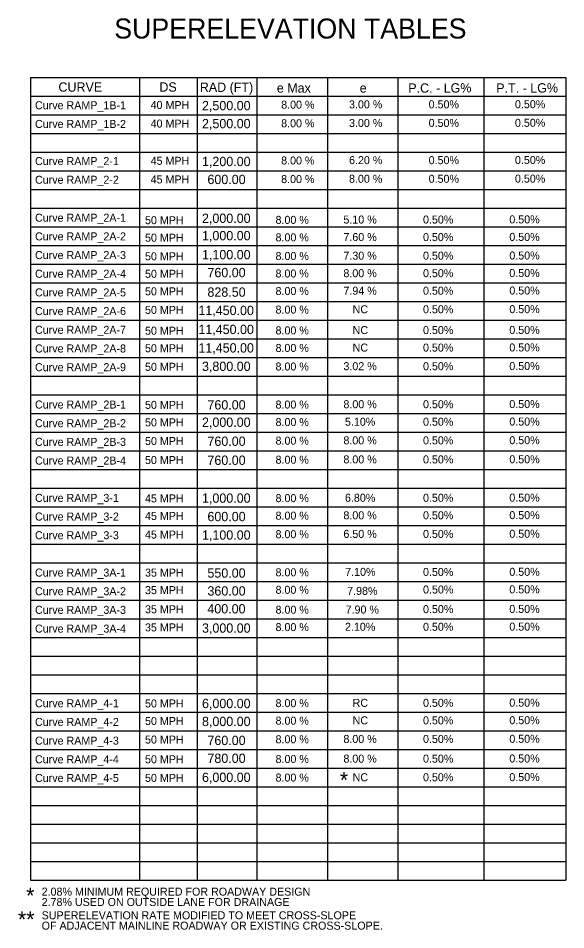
# Model space of a CAD drawing. Extents: x 1609180 to 1612299, y 1092317 to 1096201.
# Drawn here: x 1610132 to 1610543, y 1095399 to 1096082 of the extents above; entities that cross this region are included whole.
import ezdxf

# ---------------------------------------------------------------- set-up
doc = ezdxf.new("R2010")
doc.units = 0
for name, color, linetype in [('Level 1', 7, 'Continuous'), ('RD_HC_Data_50', 7, 'Continuous'), ('RD_SHT_TX', 7, 'Continuous')]:
    doc.layers.add(name, color=color, linetype=linetype)

msp = doc.modelspace()

# ---------------------------------------------------------------- linework, layer by layer
at = {"layer": 'RD_SHT_TX'}
for p, q in [((1610141.1, 1096037.78), (1610141.1, 1095435.78)), ((1610141.1, 1096037.78), (1610542.55, 1096037.78)), ((1610222.73, 1096037.78), (1610222.73, 1095435.78)), ((1610266.09, 1096037.78), (1610266.09, 1095435.78)), ((1610310.86, 1096037.78), (1610310.86, 1095435.78)), ((1610363.76, 1096037.78), (1610363.76, 1095435.78)), ((1610416.66, 1096037.78), (1610416.66, 1095435.78)), ((1610481.04, 1096037.78), (1610481.04, 1095435.78)), ((1610542.55, 1096037.78), (1610542.55, 1095435.78)), ((1610141.1, 1096023.78), (1610542.55, 1096023.78)), ((1610141.1, 1096009.78), (1610542.55, 1096009.78)), ((1610141.1, 1095995.78), (1610542.55, 1095995.78)), ((1610141.1, 1095981.78), (1610542.55, 1095981.78)), ((1610141.1, 1095967.78), (1610542.55, 1095967.78)), ((1610141.1, 1095953.78), (1610542.55, 1095953.78)), ((1610141.1, 1095939.78), (1610542.55, 1095939.78)), ((1610141.1, 1095925.78), (1610542.55, 1095925.78)), ((1610141.1, 1095911.78), (1610542.55, 1095911.78)), ((1610141.1, 1095897.78), (1610542.55, 1095897.78)), ((1610141.1, 1095883.78), (1610542.55, 1095883.78)), ((1610141.1, 1095869.78), (1610542.55, 1095869.78)), ((1610141.1, 1095855.78), (1610542.55, 1095855.78)), ((1610141.1, 1095841.78), (1610542.55, 1095841.78)), ((1610141.1, 1095827.78), (1610542.55, 1095827.78)), ((1610141.1, 1095813.78), (1610542.55, 1095813.78)), ((1610141.1, 1095799.78), (1610542.55, 1095799.78)), ((1610141.1, 1095785.78), (1610542.55, 1095785.78)), ((1610141.1, 1095771.78), (1610542.55, 1095771.78)), ((1610141.1, 1095757.78), (1610542.55, 1095757.78)), ((1610141.1, 1095743.78), (1610542.55, 1095743.78)), ((1610141.1, 1095729.78), (1610542.55, 1095729.78)), ((1610141.1, 1095715.78), (1610542.55, 1095715.78)), ((1610141.1, 1095701.78), (1610542.55, 1095701.78)), ((1610141.1, 1095687.78), (1610542.55, 1095687.78)), ((1610141.1, 1095673.78), (1610542.55, 1095673.78)), ((1610141.1, 1095659.78), (1610542.55, 1095659.78)), ((1610141.1, 1095645.78), (1610542.55, 1095645.78)), ((1610141.1, 1095631.78), (1610542.55, 1095631.78)), ((1610141.1, 1095617.78), (1610542.55, 1095617.78)), ((1610141.1, 1095603.78), (1610542.55, 1095603.78)), ((1610141.1, 1095589.78), (1610542.55, 1095589.78)), ((1610141.1, 1095575.78), (1610542.55, 1095575.78)), ((1610141.1, 1095561.78), (1610542.55, 1095561.78)), ((1610141.1, 1095547.78), (1610542.55, 1095547.78)), ((1610141.1, 1095533.78), (1610542.55, 1095533.78)), ((1610141.1, 1095519.78), (1610542.55, 1095519.78)), ((1610141.1, 1095505.78), (1610542.55, 1095505.78)), ((1610141.1, 1095491.78), (1610542.55, 1095491.78)), ((1610141.1, 1095477.78), (1610542.55, 1095477.78)), ((1610141.1, 1095463.78), (1610542.55, 1095463.78)), ((1610141.1, 1095449.78), (1610542.55, 1095449.78)), ((1610141.1, 1095435.78), (1610542.55, 1095435.78))]:
    msp.add_line(p, q, dxfattribs=at)

# ---------------------------------------------------------------- texts
at = {"layer": 'Level 1'}
for s, p in [('Curve RAMP_2B-4            ', (1610144.47, 1095747.49)), ('Curve RAMP_3-1             ', (1610144.47, 1095719.49)), ('Curve RAMP_3-2             ', (1610144.47, 1095705.49))]:
    msp.add_text(s, height=6, dxfattribs=at).set_placement(p)
at = {"layer": 'RD_HC_Data_50'}
for s, p in [('P.C. - LG%', (1610424.45, 1096026.23)), ('P.T. - LG%', (1610490.43, 1096026.23))]:
    msp.add_text(s, height=7, rotation=0.2225, dxfattribs=at).set_placement(p)
for s, p in [('3.00 %', (1610379.99, 1096014.54)), ('0.50%', (1610439.7, 1096014.54)), ('0.50%', (1610504.43, 1096014.65)), ('40 MPH', (1610231.18, 1096014.07)), ('8.00 %', (1610329.08, 1096014.3)), ('40 MPH', (1610231.18, 1096000.12)), ('8.00 %', (1610329.08, 1096000.35)), ('3.00 %', (1610379.99, 1096000.59)), ('0.50%', (1610439.7, 1096000.59)), ('0.50%', (1610504.43, 1096000.71)), ('45 MPH', (1610231.18, 1095972.22)), ('8.00 %', (1610329.08, 1095972.46)), ('6.20 %', (1610379.99, 1095972.69)), ('0.50%', (1610439.7, 1095972.69)), ('0.50%', (1610504.43, 1095972.81)), ('45 MPH', (1610231.18, 1095958.27)), ('8.00 %', (1610329.08, 1095958.51)), ('8.00 %', (1610379.99, 1095958.74)), ('0.50%', (1610439.7, 1095958.74)), ('0.50%', (1610504.43, 1095958.86)), ('50 MPH', (1610226.97, 1095927.7)), ('8.00 %', (1610324.87, 1095927.93)), ('5.10 %', (1610375.78, 1095928.17)), ('0.50%', (1610435.48, 1095928.17)), ('0.50%', (1610500.22, 1095928.28)), ('50 MPH', (1610226.97, 1095914.57)), ('8.00 %', (1610324.87, 1095914.8)), ('7.60 %', (1610375.78, 1095915.04)), ('0.50%', (1610435.48, 1095915.04)), ('0.50%', (1610500.22, 1095915.15)), ('50 MPH', (1610226.97, 1095900.62)), ('8.00 %', (1610324.87, 1095900.85)), ('7.30 %', (1610375.78, 1095901.09)), ('0.50%', (1610435.48, 1095901.09)), ('0.50%', (1610500.22, 1095901.21)), ('50 MPH', (1610226.97, 1095887.49)), ('8.00 %', (1610324.87, 1095887.73)), ('8.00 %', (1610375.78, 1095887.96)), ('0.50%', (1610435.48, 1095887.96)), ('0.50%', (1610500.22, 1095888.08)), ('50 MPH', (1610226.97, 1095874.36)), ('8.00 %', (1610324.87, 1095874.6)), ('7.94 %', (1610375.78, 1095874.83)), ('0.50%', (1610435.48, 1095874.83)), ('0.50%', (1610500.22, 1095874.95)), ('50 MPH', (1610226.97, 1095860.42)), ('8.00 %', (1610324.87, 1095860.65)), ('NC', (1610382.68, 1095860.89)), ('0.50%', (1610435.48, 1095860.89)), ('0.50%', (1610500.22, 1095861)), ('50 MPH', (1610226.97, 1095844.83)), ('8.00 %', (1610324.87, 1095845.06)), ('NC', (1610382.68, 1095845.3)), ('0.50%', (1610435.48, 1095845.3)), ('0.50%', (1610500.22, 1095845.41)), ('50 MPH', (1610226.97, 1095831.7)), ('8.00 %', (1610324.87, 1095831.93)), ('NC', (1610382.68, 1095832.17)), ('0.50%', (1610435.48, 1095832.17)), ('0.50%', (1610500.22, 1095832.29)), ('50 MPH', (1610226.97, 1095817.75)), ('8.00 %', (1610324.87, 1095817.99)), ('3.02 %', (1610375.78, 1095818.22)), ('0.50%', (1610435.48, 1095818.22)), ('0.50%', (1610500.22, 1095818.34)), ('50 MPH', (1610226.97, 1095789.24)), ('8.00 %', (1610324.87, 1095789.47)), ('8.00 %', (1610375.78, 1095789.71)), ('0.50%', (1610435.48, 1095789.71)), ('0.50%', (1610500.22, 1095789.83)), ('50 MPH', (1610226.97, 1095776.11)), ('8.00 %', (1610324.87, 1095776.35)), ('5.10%', (1610376.94, 1095776.58)), ('0.50%', (1610435.48, 1095776.58)), ('0.50%', (1610500.22, 1095776.7)), ('50 MPH', (1610226.97, 1095762.16)), ('8.00 %', (1610324.87, 1095762.4)), ('8.00 %', (1610375.78, 1095762.63)), ('0.50%', (1610435.48, 1095762.63)), ('0.50%', (1610500.22, 1095762.75)), ('8.00 %', (1610324.87, 1095748.1)), ('8.00 %', (1610375.78, 1095748.33)), ('0.50%', (1610435.48, 1095748.33)), ('0.50%', (1610500.22, 1095748.45)), ('50 MPH', (1610226.97, 1095747.86)), ('45 MPH', (1610226.97, 1095719.09)), ('8.00 %', (1610324.87, 1095719.32)), ('6.80%', (1610376.94, 1095719.56)), ('0.50%', (1610435.48, 1095719.56)), ('0.50%', (1610500.22, 1095719.67)), ('45 MPH', (1610226.97, 1095705.96)), ('8.00 %', (1610324.87, 1095706.19)), ('8.00 %', (1610375.78, 1095706.43)), ('0.50%', (1610435.48, 1095706.43)), ('0.50%', (1610500.22, 1095706.55)), ('45 MPH', (1610226.97, 1095692.01)), ('8.00 %', (1610324.87, 1095692.25)), ('6.50 %', (1610375.78, 1095692.48)), ('0.50%', (1610435.48, 1095692.48)), ('0.50%', (1610500.22, 1095692.6)), ('35 MPH', (1610226.97, 1095663.46)), ('8.00 %', (1610324.87, 1095663.7)), ('0.50%', (1610435.48, 1095663.93)), ('0.50%', (1610500.22, 1095664.05)), ('35 MPH', (1610226.97, 1095650.33)), ('8.00 %', (1610324.87, 1095650.57)), ('0.50%', (1610435.48, 1095650.8)), ('0.50%', (1610500.22, 1095650.92)), ('35 MPH', (1610226.97, 1095635.97)), ('8.00 %', (1610324.87, 1095635.66)), ('7.90 %', (1610377.43, 1095635.78)), ('0.50%', (1610435.48, 1095636.11)), ('0.50%', (1610500.22, 1095636.23)), ('35 MPH', (1610226.97, 1095622.39)), ('8.00 %', (1610324.87, 1095622.62)), ('2.10%', (1610376.94, 1095622.85)), ('0.50%', (1610435.48, 1095622.85)), ('0.50%', (1610500.22, 1095622.97)), ('50 MPH', (1610226.97, 1095565.36)), ('8.00 %', (1610324.87, 1095565.6)), ('RC', (1610382.68, 1095565.83)), ('0.50%', (1610435.48, 1095565.83)), ('0.50%', (1610500.22, 1095565.95)), ('50 MPH', (1610226.97, 1095552.23)), ('8.00 %', (1610324.87, 1095552.47)), ('NC', (1610382.68, 1095552.7)), ('0.50%', (1610435.48, 1095552.7)), ('0.50%', (1610500.22, 1095552.82)), ('50 MPH', (1610226.97, 1095538.29)), ('8.00 %', (1610324.87, 1095538.52)), ('8.00 %', (1610375.78, 1095538.75)), ('0.50%', (1610435.48, 1095538.75)), ('0.50%', (1610500.22, 1095538.87)), ('50 MPH', (1610226.97, 1095523.52)), ('8.00 %', (1610324.87, 1095523.75)), ('8.00 %', (1610375.78, 1095523.99)), ('0.50%', (1610435.48, 1095523.99)), ('0.50%', (1610500.22, 1095524.1)), ('50 MPH', (1610226.97, 1095509.57)), ('8.00 %', (1610324.87, 1095509.8)), ('NC', (1610382.68, 1095510.04)), ('0.50%', (1610435.48, 1095510.04)), ('0.50%', (1610500.22, 1095510.15))]:
    msp.add_text(s, height=6, dxfattribs=at).set_placement(p)
at = {"layer": 'RD_SHT_TX'}
for s, height, p in [('SUPERELEVATION TABLES', 15, (1610203.9, 1096066.88)), ('RAD (FT)', 7, (1610268.07, 1096026.9)), ('CURVE', 7, (1610162.05, 1096027.01)), ('DS', 7, (1610237.75, 1096027.04)), ('e Max', 7, (1610325.82, 1096026.33)), ('e', 7, (1610388, 1096026.33)), ('Curve RAMP_1B-1            ', 6, (1610144.47, 1096013.85)), ('2,500.00', 7, (1610269.71, 1096013.09)), ('Curve RAMP_1B-2            ', 6, (1610144.47, 1095999.85)), ('2,500.00', 7, (1610269.71, 1095999.6)), ('Curve RAMP_2-1            ', 6, (1610144.47, 1095972.01)), ('1,200.00', 7, (1610269.71, 1095971.23)), ('Curve RAMP_2-2            ', 6, (1610144.47, 1095958.01)), ('600.00', 7, (1610273.79, 1095957.74)), ('Curve RAMP_2A-1            ', 6, (1610144.47, 1095929.54)), ('2,000.00', 7, (1610269.71, 1095928.62)), ('Curve RAMP_2A-2            ', 6, (1610144.47, 1095915.54)), ('1,000.00', 7, (1610269.71, 1095915.6)), ('Curve RAMP_2A-3            ', 6, (1610144.47, 1095901.54)), ('1,100.00', 7, (1610269.71, 1095901.35)), ('Curve RAMP_2A-4            ', 6, (1610144.47, 1095887.54)), ('760.00', 7, (1610273.79, 1095887.93)), ('Curve RAMP_2A-5            ', 6, (1610144.47, 1095873.54)), ('828.50', 7, (1610273.79, 1095873.28)), ('Curve RAMP_2A-6            ', 6, (1610144.47, 1095859.54)), ('11,450.00', 7, (1610266.99, 1095859.54)), ('Curve RAMP_2A-7            ', 6, (1610144.47, 1095845.49)), ('11,450.00', 7, (1610266.99, 1095845.3)), ('Curve RAMP_2A-8            ', 6, (1610144.47, 1095831.49)), ('11,450.00', 7, (1610266.99, 1095831.46)), ('Curve RAMP_2A-9            ', 6, (1610144.47, 1095817.49)), ('3,800.00', 7, (1610269.71, 1095817.63)), ('Curve RAMP_2B-1            ', 6, (1610144.47, 1095789.49)), ('760.00', 7, (1610273.79, 1095788.74)), ('Curve RAMP_2B-2            ', 6, (1610144.47, 1095775.49)), ('2,000.00', 7, (1610269.71, 1095775.71)), ('760.00', 7, (1610273.79, 1095761.47)), ('Curve RAMP_2B-3            ', 6, (1610144.47, 1095761.49)), ('760.00', 7, (1610273.79, 1095747.23)), ('1,000.00', 7, (1610269.71, 1095718.82)), ('600.00', 7, (1610273.79, 1095704.99)), ('Curve RAMP_3-3             ', 6, (1610144.47, 1095691.49)), ('1,100.00', 7, (1610269.71, 1095691.15)), ('Curve RAMP_3A-1            ', 6, (1610144.47, 1095663.49)), ('550.00', 7, (1610273.79, 1095662.67)), ('7.10%', 6, (1610377.11, 1095664.04)), ('Curve RAMP_3A-2            ', 6, (1610144.47, 1095649.49)), ('360.00', 7, (1610273.79, 1095649.24)), ('7.98%', 6, (1610378.59, 1095649.78)), ('Curve RAMP_3A-3            ', 6, (1610144.47, 1095635.55)), ('400.00', 7, (1610273.73, 1095635.85)), ('Curve RAMP_3A-4           ', 6, (1610144.47, 1095621.49)), ('3,000.00', 7, (1610269.71, 1095621.4)), ('Curve RAMP_4-1             ', 6, (1610144.47, 1095565.49)), ('6,000.00', 7, (1610269.71, 1095564.84)), ('Curve RAMP_4-2             ', 6, (1610144.47, 1095551.49)), ('8,000.00', 7, (1610269.71, 1095551.41)), ('Curve RAMP_4-3             ', 6, (1610144.47, 1095537.49)), ('760.00', 7, (1610273.79, 1095537.17)), ('Curve RAMP_4-4             ', 6, (1610144.47, 1095523.49)), ('780.00', 7, (1610273.79, 1095523.74)), ('Curve RAMP_4-5             ', 6, (1610144.47, 1095509.49)), ('6,000.00', 7, (1610269.71, 1095509.5)), ('*', 12, (1610373.11, 1095504.98)), ('*', 12, (1610137.79, 1095418.28)), ('2.08% MINIMUM REQUIRED FOR ROADWAY DESIGN', 6, (1610149.45, 1095424.28)), ('2.78% USED ON OUTSIDE LANE FOR DRAINAGE', 6, (1610149.45, 1095416.51)), ('**', 12, (1610131.62, 1095400.54)), ('SUPERELEVATION RATE MODIFIED TO MEET CROSS-SLOPE ', 6, (1610149.45, 1095406.54)), ('OF ADJACENT MAINLINE ROADWAY OR EXISTING CROSS-SLOPE.', 6, (1610149.45, 1095398.78))]:
    msp.add_text(s, height=height, dxfattribs=at).set_placement(p)

doc.saveas('drawing.dxf')
